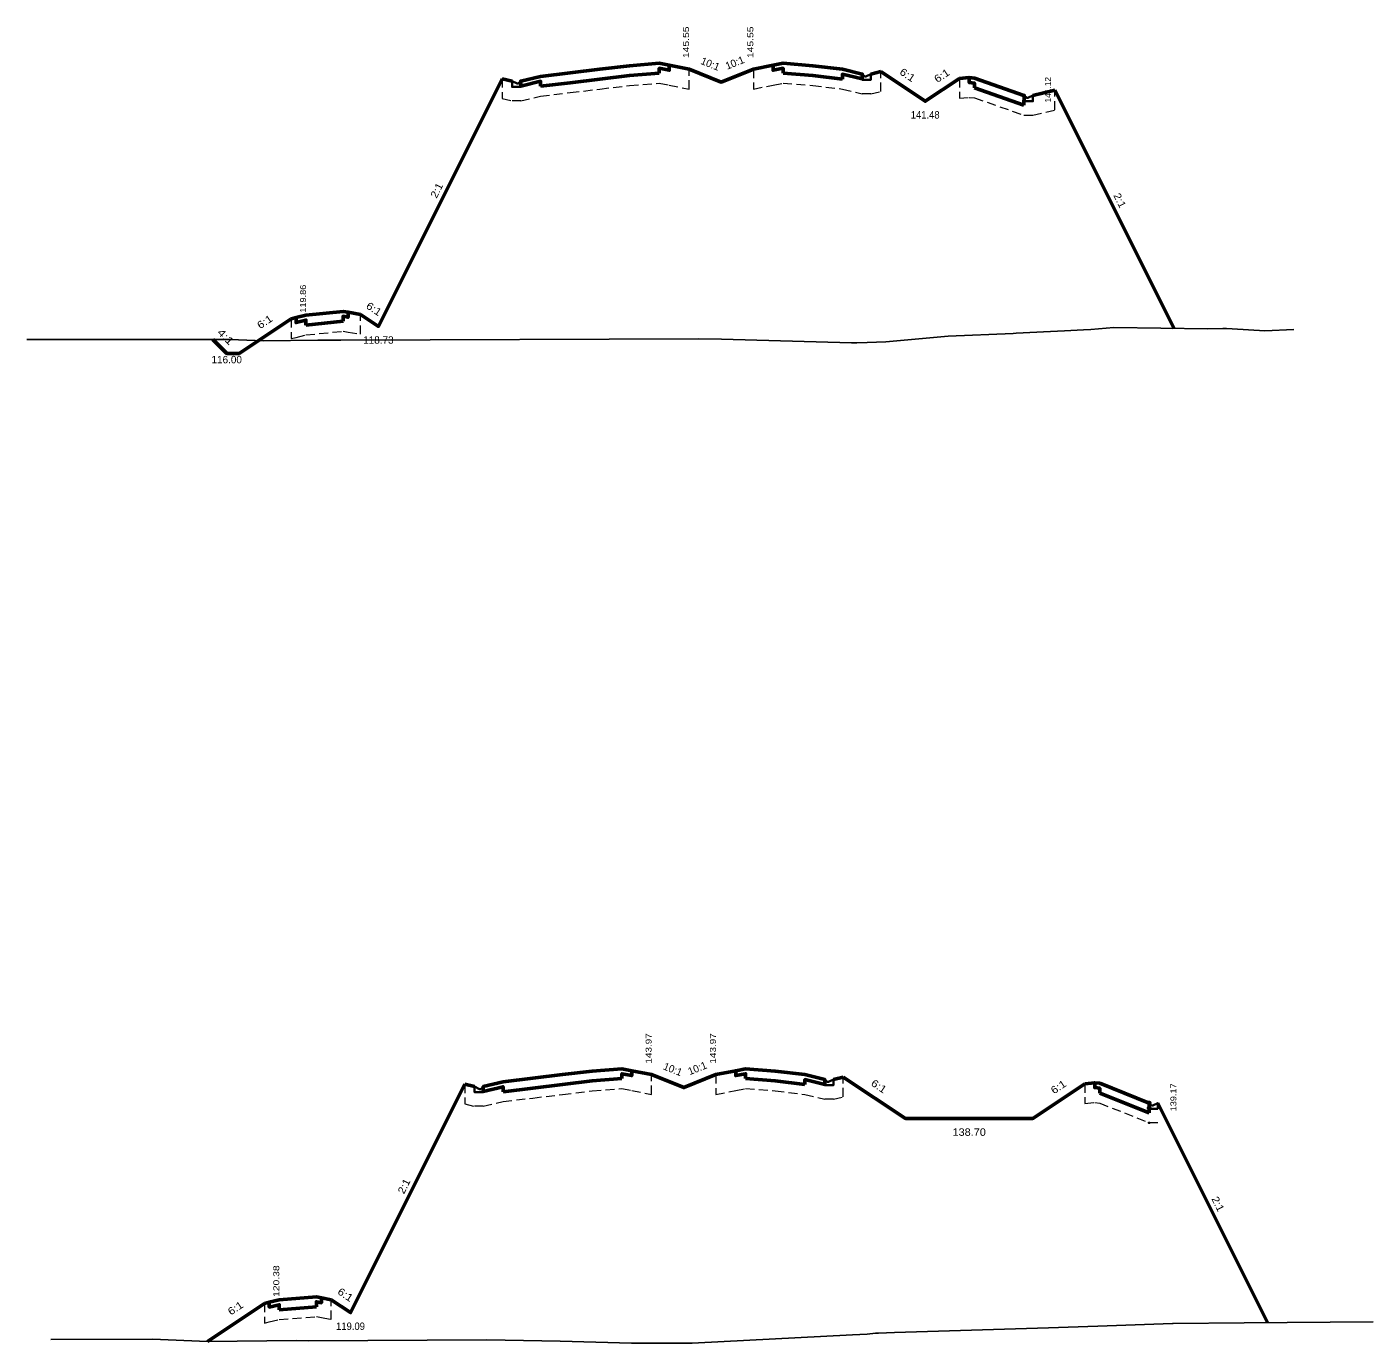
# Model space of a CAD drawing. Extents: x 72769 to 76375, y 67856 to 87579.
# Drawn here: x 72775 to 73319, y 86291 to 86823 of the extents above; entities that cross this region are included whole.
import ezdxf
from ezdxf.enums import TextEntityAlignment as Align

# ---------------------------------------------------------------- set-up
doc = ezdxf.new("R2010")
doc.units = 0
doc.header["$LTSCALE"] = 1.2
doc.header["$PDMODE"] = 32
doc.header["$PDSIZE"] = 0.6
doc.linetypes.add('MEDIUM_DASHED', pattern=[4.5, 3, -1.5])
for name, color, linetype, lineweight in [('1', 7, 'Continuous', 53), ('10', 7, 'Continuous', 53), ('11', 7, 'Continuous', 53), ('12', 7, 'Continuous', 53), ('13', 7, 'MEDIUM_DASHED', 13), ('61', 7, 'Continuous', 25)]:
    doc.layers.add(name, color=color, linetype=linetype, lineweight=lineweight)
for name, color, linetype in [('21', 7, 'Continuous'), ('50', 7, 'Continuous'), ('51', 7, 'Continuous'), ('52', 7, 'Continuous')]:
    doc.layers.add(name, color=color, linetype=linetype)

msp = doc.modelspace()

# ---------------------------------------------------------------- linework, layer by layer
at = {"layer": '1'}
for p, q in [((72994.99, 86804.339), (73006.99, 86805.779)), ((73006.99, 86805.779), (73018.99, 86807.219)), ((73018.99, 86807.219), (73030.99, 86808.179)), ((73080.991, 86808.179), (73092.99, 86807.219)), ((73092.99, 86807.219), (73104.99, 86805.779)), ((72982.99, 86802.899), (72994.99, 86804.339)), ((72982.99, 86798.899), (72994.99, 86800.339)), ((72994.99, 86800.339), (73006.99, 86801.779)), ((73006.99, 86801.779), (73018.99, 86803.219)), ((73018.99, 86803.219), (73030.99, 86804.179)), ((73080.991, 86804.179), (73092.99, 86803.219)), ((73092.99, 86803.219), (73104.99, 86801.779)), ((73158.361, 86802.213), (73178.362, 86795.223)), ((73158.361, 86798.213), (73178.362, 86791.223)), ((72888.19, 86706.389), (72903.209, 86707.925)), ((72888.19, 86702.389), (72903.209, 86703.925)), ((72967.847, 86396.576), (72979.847, 86398.016)), ((72979.847, 86398.016), (72991.847, 86399.456)), ((72991.847, 86399.456), (73003.847, 86400.896)), ((73003.847, 86400.896), (73015.847, 86401.856)), ((73003.847, 86396.896), (73015.847, 86397.856)), ((73065.848, 86401.856), (73077.847, 86400.896)), ((73065.848, 86397.856), (73077.847, 86396.896)), ((73077.847, 86400.896), (73089.847, 86399.456)), ((72967.847, 86392.576), (72979.847, 86394.016)), ((72979.847, 86394.016), (72991.847, 86395.456)), ((72991.847, 86395.456), (73003.847, 86396.896)), ((73077.847, 86396.896), (73089.847, 86395.456)), ((73208.965, 86395.982), (73228.965, 86387.999)), ((73208.965, 86391.982), (73228.965, 86383.999)), ((72877.375, 86308.471), (72892.389, 86309.685)), ((72877.375, 86304.471), (72892.389, 86305.685))]:
    msp.add_line(p, q, dxfattribs=at)
at = {"layer": '10'}
for p, q in [((73034.992, 86807.378), (73042.993, 86805.778)), ((73068.992, 86805.779), (73076.992, 86807.379)), ((72967.492, 86801.939), (72971.492, 86800.979)), ((73116.492, 86803.858), (73120.491, 86804.818)), ((73152.248, 86802.062), (73156.249, 86802.382)), ((73181.973, 86795.184), (73190.902, 86797.326)), ((72882.184, 86704.949), (72884.185, 86705.429)), ((72905.216, 86707.569), (72910.212, 86706.682)), ((73019.849, 86401.056), (73027.85, 86399.456)), ((73053.849, 86399.456), (73061.849, 86401.056)), ((73101.349, 86397.536), (73105.348, 86398.495)), ((72952.349, 86395.617), (72956.349, 86394.657)), ((73202.965, 86395.744), (73206.965, 86396.22)), ((72871.37, 86307.031), (72873.371, 86307.511)), ((72894.391, 86309.286), (72898.394, 86308.49))]:
    msp.add_line(p, q, dxfattribs=at)
at = {"layer": '10', "lineweight": 35}
for points in [[(72974.992, 86800.979), (72974.992, 86798.646), (72971.492, 86798.646), (72971.492, 86800.979), (72973.492, 86799.979), (72973.992, 86799.979)], [(73112.992, 86803.858), (73113.992, 86802.858), (73114.492, 86802.858), (73116.492, 86803.858), (73116.492, 86801.525), (73112.992, 86801.525)], [(73178.473, 86795.184), (73179.473, 86794.184), (73179.973, 86794.184), (73181.973, 86795.184), (73181.973, 86792.851), (73178.473, 86792.851)], [(73097.849, 86397.536), (73098.849, 86396.536), (73099.349, 86396.536), (73101.349, 86397.536), (73101.349, 86395.202), (73097.849, 86395.202)], [(72959.849, 86394.657), (72959.849, 86392.323), (72956.349, 86392.323), (72956.349, 86394.657), (72958.349, 86393.657), (72958.849, 86393.657)], [(73228.965, 86387.999), (73229.965, 86386.999), (73230.466, 86386.999), (73232.466, 86387.999), (73232.466, 86385.666), (73228.965, 86385.666)]]:
    msp.add_lwpolyline(points, close=True, dxfattribs=at)
at = {"layer": '11'}
for p, q in [((73228.965, 86387.999), (73228.965, 86385.999)), ((73228.965, 86385.999), (73228.965, 86383.999))]:
    msp.add_line(p, q, dxfattribs=at)
for points in [[(73030.99, 86808.179), (73034.992, 86807.378), (73034.992, 86805.378), (73030.99, 86806.179), (73030.99, 86804.179)], [(73080.991, 86804.179), (73080.991, 86806.179), (73076.992, 86805.379), (73076.992, 86807.379), (73080.991, 86808.179)], [(73104.99, 86805.779), (73112.992, 86803.858), (73112.992, 86801.858), (73104.99, 86803.779), (73104.99, 86801.779)], [(72982.99, 86798.899), (72982.99, 86800.899), (72974.992, 86798.979), (72974.992, 86800.979), (72982.99, 86802.899)], [(73158.361, 86798.213), (73158.361, 86800.213), (73156.249, 86800.382), (73156.249, 86802.382), (73158.361, 86802.213)], [(73178.362, 86795.223), (73178.473, 86795.184), (73178.473, 86793.184), (73178.362, 86793.223), (73178.362, 86791.223)], [(72903.209, 86707.925), (72905.216, 86707.569), (72905.216, 86705.569), (72903.209, 86705.925), (72903.209, 86703.925)], [(72888.19, 86702.389), (72888.19, 86704.389), (72884.185, 86703.429), (72884.185, 86705.429), (72888.19, 86706.389)], [(73015.847, 86401.856), (73019.849, 86401.056), (73019.849, 86399.056), (73015.847, 86399.856), (73015.847, 86397.856)], [(73065.848, 86397.856), (73065.848, 86399.856), (73061.849, 86399.056), (73061.849, 86401.056), (73065.848, 86401.856)], [(73089.847, 86399.456), (73097.849, 86397.536), (73097.849, 86395.536), (73089.847, 86397.456), (73089.847, 86395.456)], [(72967.847, 86392.576), (72967.847, 86394.576), (72959.849, 86392.657), (72959.849, 86394.657), (72967.847, 86396.576)], [(73208.965, 86391.982), (73208.965, 86393.982), (73206.965, 86394.22), (73206.965, 86396.22), (73208.965, 86395.982)], [(72877.375, 86304.471), (72877.375, 86306.471), (72873.371, 86305.511), (72873.371, 86307.511), (72877.375, 86308.471)], [(72892.389, 86309.685), (72894.391, 86309.286), (72894.391, 86307.286), (72892.389, 86307.685), (72892.389, 86305.685)]]:
    msp.add_lwpolyline(points, dxfattribs=at)
for p in [(73228.965, 86387.999), (73228.965, 86385.999)]:
    msp.add_point(p, dxfattribs=at)
at = {"layer": '12'}
for p, q in [((73190.902, 86797.326), (73239.062, 86701.038)), ((73232.466, 86387.999), (73276.832, 86299.269)), ((72848.317, 86291.677), (72871.37, 86307.031))]:
    msp.add_line(p, q, dxfattribs=at)
for points in [[(73042.993, 86805.778), (73055.992, 86800.579), (73068.992, 86805.779)], [(72910.212, 86706.682), (72917.45, 86701.856), (72967.492, 86801.939)], [(73120.491, 86804.818), (73138.437, 86792.854), (73152.248, 86802.062)], [(72850.498, 86696.602), (72856.156, 86690.949), (72861.162, 86690.949), (72882.184, 86704.949)], [(73027.85, 86399.456), (73040.849, 86394.256), (73053.849, 86399.456)], [(73105.348, 86398.495), (73130.476, 86381.744), (73181.965, 86381.744), (73202.965, 86395.744)], [(72898.394, 86308.49), (72906.188, 86303.294), (72952.349, 86395.617)]]:
    msp.add_lwpolyline(points, dxfattribs=at)
at = {"layer": '13'}
for p, q in [((73018.99, 86799.219), (73030.99, 86800.179)), ((73030.99, 86800.179), (73034.992, 86799.378)), ((73076.992, 86799.379), (73080.991, 86800.179)), ((73080.991, 86800.179), (73092.99, 86799.219)), ((72974.992, 86792.979), (72982.99, 86794.899)), ((72982.99, 86794.899), (72994.99, 86796.339)), ((72994.99, 86796.339), (73006.99, 86797.779)), ((73006.99, 86797.779), (73018.99, 86799.219)), ((73092.99, 86799.219), (73104.99, 86797.779)), ((73104.99, 86797.779), (73112.992, 86795.858)), ((73116.492, 86795.858), (73112.992, 86795.858)), ((72974.992, 86792.979), (72971.492, 86792.979)), ((73156.249, 86794.382), (73158.361, 86794.213)), ((73158.361, 86794.213), (73178.362, 86787.223)), ((73178.362, 86787.223), (73178.473, 86787.184)), ((73178.362, 86787.223), (73181.973, 86787.184)), ((72884.185, 86697.429), (72888.19, 86698.389)), ((72888.19, 86698.389), (72903.209, 86699.925)), ((72903.209, 86699.925), (72905.216, 86699.569)), ((72991.847, 86391.456), (73003.847, 86392.896)), ((73003.847, 86392.896), (73015.847, 86393.856)), ((73015.847, 86393.856), (73019.849, 86393.056)), ((73061.849, 86393.056), (73065.848, 86393.856)), ((73065.848, 86393.856), (73077.847, 86392.896)), ((73077.847, 86392.896), (73089.847, 86391.456)), ((72959.849, 86386.657), (72956.349, 86386.657)), ((72959.849, 86386.657), (72967.847, 86388.576)), ((72967.847, 86388.576), (72979.847, 86390.016)), ((72979.847, 86390.016), (72991.847, 86391.456)), ((73089.847, 86391.456), (73097.849, 86389.536)), ((73101.349, 86389.536), (73097.849, 86389.536)), ((73206.965, 86388.22), (73208.965, 86387.982)), ((73208.965, 86387.982), (73228.965, 86379.999)), ((73232.466, 86379.999), (73228.965, 86379.999)), ((72873.371, 86299.511), (72877.375, 86300.471)), ((72877.375, 86300.471), (72892.389, 86301.685)), ((72892.389, 86301.685), (72894.391, 86301.286))]:
    msp.add_line(p, q, dxfattribs=at)
for points in [[(73034.992, 86799.378), (73042.993, 86797.778), (73042.993, 86805.778)], [(73068.992, 86805.779), (73068.992, 86797.779), (73076.992, 86799.379)], [(72967.492, 86801.939), (72967.492, 86793.939), (72971.492, 86792.979)], [(73116.492, 86795.858), (73120.491, 86796.818), (73120.491, 86804.818)], [(73152.248, 86802.062), (73152.248, 86794.062), (73156.249, 86794.382)], [(73181.973, 86787.184), (73190.902, 86789.326), (73190.902, 86797.326)], [(72882.184, 86704.949), (72882.184, 86696.949), (72884.185, 86697.429)], [(72905.216, 86699.569), (72910.212, 86698.682), (72910.212, 86706.682)], [(73019.849, 86393.056), (73027.85, 86391.456), (73027.85, 86399.456)], [(73053.849, 86399.456), (73053.849, 86391.456), (73061.849, 86393.056)], [(73101.349, 86389.536), (73105.348, 86390.495), (73105.348, 86398.495)], [(72952.349, 86395.617), (72952.349, 86387.617), (72956.349, 86386.657)], [(73202.965, 86395.744), (73202.965, 86387.744), (73206.965, 86388.22)], [(72871.37, 86307.031), (72871.37, 86299.031), (72873.371, 86299.511)], [(72894.391, 86301.286), (72898.394, 86300.49), (72898.394, 86308.49)]]:
    msp.add_lwpolyline(points, dxfattribs=at)
msp.add_point((73228.965, 86379.999), dxfattribs=at)
at = {"layer": '61'}
for points in [[(72775.399, 86696.517), (72857.477, 86696.61), (72871.064, 86696.083), (72892.958, 86696.258), (72902.317, 86696.229), (73046.774, 86696.843), (73056.11, 86696.693), (73108.635, 86695.24), (73110.841, 86695.261), (73115.014, 86695.346), (73122.578, 86695.641), (73147.756, 86697.865), (73173.946, 86698.949), (73174.016, 86698.949), (73175.221, 86699.08), (73189.125, 86699.829), (73194.769, 86700.046), (73202.427, 86700.498), (73205.404, 86700.55), (73214.636, 86701.364), (73252.665, 86700.857), (73258.687, 86700.976), (73260.218, 86701.033), (73262.493, 86700.877), (73275.768, 86700.089), (73287.484, 86700.624)], [(72785.053, 86292.493), (72826.091, 86292.539), (72848.404, 86291.674), (72884.358, 86291.961), (72889.035, 86291.947), (72961.228, 86292.253), (72990.906, 86291.779), (73019.739, 86290.981), (73044.292, 86290.981), (73109.086, 86294.341), (73114.942, 86294.583), (73118.37, 86294.949), (73119.563, 86294.949), (73125.999, 86295.213), (73188.277, 86297.201), (73208.263, 86297.756), (73238.347, 86298.949), (73238.609, 86298.949), (73267.353, 86299.195), (73319.464, 86299.599)]]:
    msp.add_lwpolyline(points, dxfattribs=at)

# ---------------------------------------------------------------- texts
at = {"layer": '21'}
for s, width, p in [(' 145.55', 1.3, (73042.989, 86809.139)), (' 145.55', 1.3, (73068.989, 86809.139)), (' 141.12', 1.05, (73189.251, 86791.421)), (' 119.86', 1.15, (72888.189, 86706.389)), (' 143.97', 1.25, (73027.847, 86402.816)), (' 143.97', 1.25, (73053.847, 86402.816)), (' 139.17', 1.15, (73239.966, 86383.61)), (' 120.38', 1.3, (72877.375, 86308.471))]:
    msp.add_text(s, height=2.4, rotation=90, dxfattribs=dict(at, width=width)).set_placement(p)
at = {"layer": '50'}
for rotation, p in [(338.199, (73051.05, 86806.555)), (21.801, (73062.049, 86807.002)), (338.199, (73035.907, 86400.233)), (21.801, (73046.906, 86400.679))]:
    msp.add_text('10:1', height=3, rotation=rotation, dxfattribs=at).set_placement(p, align=Align.CENTER)
for s, rotation, width, p in [('6:1', 326.31, 1.15, (73130.46, 86802.227)), ('6:1', 33.69, 1.15, (73146.01, 86801.958)), ('2:1', 63.435, 1.1, (72942.359, 86756.146)), ('2:1', 296.573, 1.1, (73215.765, 86752.089)), ('6:1', 326.31, 1.15, (72914.827, 86707.66)), ('6:1', 33.663, 1.15, (72872.34, 86702.449)), ('4:1', 315.03, 1.3, (72854.629, 86696.598)), ('6:1', 326.31, 1.15, (73118.908, 86393.511)), ('6:1', 33.69, 1.15, (73193.132, 86393.244)), ('2:1', 63.435, 1.1, (72929.156, 86353.704)), ('2:1', 296.566, 1.1, (73255.432, 86346.541)), ('6:1', 326.31, 1.15, (72903.287, 86309.283)), ('6:1', 33.665, 1.15, (72860.511, 86303.854))]:
    msp.add_text(s, height=3, rotation=rotation, dxfattribs=dict(at, width=width)).set_placement(p, align=Align.CENTER)
at = {"layer": '51'}
msp.add_text('116.00', height=3, dxfattribs=at).set_placement((72856.151, 86686.949), align=Align.CENTER)
at = {"layer": '51', "width": 1.1}
msp.add_text('138.70', height=3, dxfattribs=at).set_placement((73156.22, 86374.744), align=Align.CENTER)
at = {"layer": '52', "width": 0.95}
for s, p in [('141.48', (73138.437, 86785.854)), ('119.09', (72906.187, 86296.294))]:
    msp.add_text(s, height=3, dxfattribs=at).set_placement(p, align=Align.CENTER)
at = {"layer": '52'}
msp.add_text('118.73', height=3, dxfattribs=at).set_placement((72917.45, 86694.856), align=Align.CENTER)

doc.saveas('drawing.dxf')
